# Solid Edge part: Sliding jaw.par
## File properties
Title: Sliding Jaw
Author: Vicky Raina
Template: Normal.par
Last saved by: Robert a Rhodes jr
Revision: 17
Application: Solid Edge
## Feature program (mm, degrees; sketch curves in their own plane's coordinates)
sketch used by "unnamed Protrusion 1" plane through (0, 0, 0) normal (0, -1, 0) x-axis (1, 0, 0)
  line (-34.0632, 44.45) -> (-34.0632, 0)
  line (-34.0632, 0) -> (5.6116, 0)
  line (5.6116, 0) -> (5.6116, 19.9608)
  line (-34.0632, 44.45) -> (-19.6102, 44.45)
  arc centre (-37.2382, 14.3002) radius 34.925 from (-19.6102, 44.45) to (-3.8245, 24.463) cw
  arc centre (2.2507, 26.3108) radius 6.35 from (-3.8245, 24.463) to (2.2507, 19.9608) ccw
  line (5.6116, 19.9608) -> (2.2507, 19.9608)
  dimension (linear) = 37.2382
extrude "unnamed Protrusion 1" add finite 69.7992 symmetric
sketch for "unnamed Protrusion 2" plane through (5.6116, 0, 9.9804) normal (1, 0, 0) x-axis (0, 1, 0)
extrude "unnamed Protrusion 2" add finite 65.0748 along -normal
sketch for "unnamed Cutout 1" plane through (-26.9258, -15.24, -27.8638) normal (0, -1, 0) x-axis (1, 0, 0)
extrude "unnamed Cutout 1" cut through along -normal
sketch for "unnamed Protrusion 3" plane through (5.6116, 0, -9.0696) normal (1, 0, 0) x-axis (0, 1, 0)
  arc centre (0, 26.5956) radius 23.9515 from (-23.8274, 29.0304) to (23.8274, 29.0304) cw
  line (-23.8274, 29.0304) -> (23.8274, 29.0304)
extrude "unnamed Protrusion 3" add through along -normal
sketch for "unnamed Hole 1" plane through (5.6116, 0, -0.1583) normal (1, 0, 0) x-axis (0, 1, 0)
hole "unnamed Hole 1" through
fillet "unnamed Round 1"
sketch for "unnamed Hole 2" plane through (-26.9258, 0, -38.1) normal (0, 0, -1) x-axis (0, 1, 0)
  hole centre (7.9375, 2.3876) bore radius 2.7686
hole "unnamed Hole 2" finite
sketch for "unnamed Hole 3" plane through (-26.9258, 0, -38.1) normal (0, 0, -1) x-axis (0, 1, 0)
  hole centre (-7.9375, 2.3876) bore radius 2.7686
hole "unnamed Hole 3" finite
sketch for "unnamed Hole 4" plane through (-34.0632, 0, 22.225) normal (-1, 0, 0) x-axis (0, -1, 0)
  hole centre (19.0754, 3.175) bore radius 3.175
hole "unnamed Hole 4" finite
sketch for "unnamed Hole 5" plane through (-34.0632, 0, 22.225) normal (-1, 0, 0) x-axis (0, -1, 0)
  hole centre (-19.0246, 3.175) bore radius 3.175
  dimension (linear) = 19.0246
hole "unnamed Hole 5" finite
chamfer "unnamed Chamfer 1"
pattern "unnamed Pattern 1" of "unnamed Hole 2", "unnamed Hole 3"
pattern "unnamed Pattern 2" of "unnamed Hole 4", "unnamed Hole 5"
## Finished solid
Body 1: solid body, 49 faces, 112 edges, 64 vertices.
  Faces by surface: plane 27, cylinder 16, torus 4, sphere 2
  Edges by curve: line 72, circle 33, intersection 7
Bounding box of the edges (mm; curved faces can reach further): 65.075 x 69.799 x 82.550, from (-59.4632, -34.8996, -38.1) to (5.6116, 34.8996, 44.45).
Cylindrical faces by radius (mm): R2.7686 x2, R3.1242 x1, R3.175 x8, R6.35 x2, R9.525 x1, R23.9515 x1, R34.925 x1
Toroidal faces (ring radius, tube radius in mm): R9.525 r3.175 x2, R31.75 r3.175 x2
Spherical faces by radius (mm): R3.175 x2
Planar faces by outward normal: +x 1, +y 4, +z 6, -x 3, -y 4, -z 7, oblique 2
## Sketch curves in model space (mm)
line (-34.0632, 0, 0) -> (5.6116, 0, 0)
line (5.6116, 0, 0) -> (5.6116, 0, 19.9608)
line (5.6116, 0, 19.9608) -> (2.2507, 0, 19.9608)
arc centre (2.2507, 0, 26.3108) radius 6.35 from (-3.8245, 0, 24.463) through (-1.5301, 0, 21.209) to (2.2507, 0, 19.9608)
arc centre (-37.2382, 0, 14.3002) radius 34.925 from (-19.6102, 0, 44.45) through (-9.8305, 0, 35.9468) to (-3.8245, 0, 24.463)
line (-34.0632, 0, 44.45) -> (-19.6102, 0, 44.45)
line (-34.0632, 0, 44.45) -> (-34.0632, 0, 0)
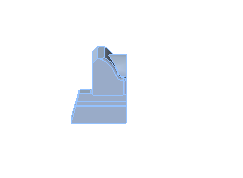
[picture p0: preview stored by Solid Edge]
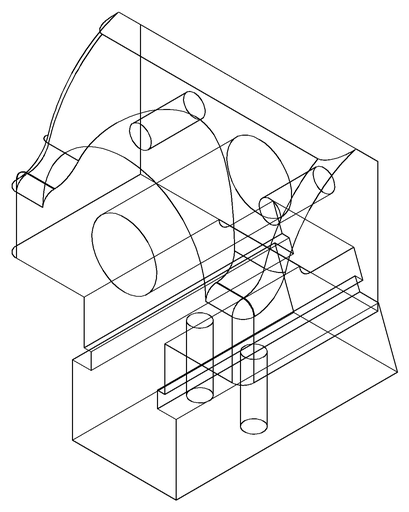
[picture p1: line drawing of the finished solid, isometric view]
